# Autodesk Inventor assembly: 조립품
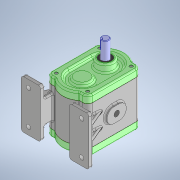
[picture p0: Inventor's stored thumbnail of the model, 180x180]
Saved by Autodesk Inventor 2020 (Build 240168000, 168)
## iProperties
Created: 2023-06
Part Number: 조립품
Document SubType Name: Assembly
Designer: oem
Author: oem
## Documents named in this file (12)
- C:\Users\oem\Desktop\730606V1008\조립품.iam
- C:\Users\oem\Desktop\730606V1008\본체.ipt
- C:\Users\oem\Desktop\730606V1008\가스켓.ipt
- C:\Users\oem\Desktop\730606V1008\니들베어링 NA 4902.ipt
- C:\Users\oem\Desktop\730606V1008\뒷커버.ipt
- C:\Users\oem\Desktop\730606V1008\메인 드라이브 기어.ipt
- C:\Users\oem\Desktop\730606V1008\묻힘키 6x6x40.ipt
- C:\Users\oem\Desktop\730606V1008\샤프트.ipt
- C:\Users\oem\Desktop\730606V1008\서브 드라이브 기어.ipt
- C:\Users\oem\Desktop\730606V1008\앞커버.ipt
- C:\Users\oem\Desktop\730606V1008\오일실 15 25 7.ipt
- C:\Users\oem\Desktop\730606V1008\육각 소켓 머리 볼트 M8 x 100.ipt
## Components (2 placed, 1 different names)
1. 가스켓:1
2. 가스켓:2
